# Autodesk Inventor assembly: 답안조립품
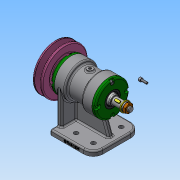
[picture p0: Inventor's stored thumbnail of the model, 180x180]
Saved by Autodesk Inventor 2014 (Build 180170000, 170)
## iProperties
Created: 2020-06
Part Number: 답안조립품
Document SubType Name: Assembly
Designer: net
Author: net
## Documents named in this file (12)
- C:\Users\net\Desktop\700606V1006\답안조립품.iam
- C:\Users\net\Desktop\700606V1006\본체.ipt
- C:\Users\net\Desktop\700606V1006\V-벨트풀리.ipt
- C:\Users\net\Desktop\700606V1006\너트 M10.ipt
- C:\Users\net\Desktop\700606V1006\베어링 6204.ipt
- C:\Users\net\Desktop\700606V1006\볼트 M4.ipt
- C:\Users\net\Desktop\700606V1006\스프링 와셔 10.ipt
- C:\Users\net\Desktop\700606V1006\오일 실 20 32 5.ipt
- C:\Users\net\Desktop\700606V1006\축.ipt
- C:\Users\net\Desktop\700606V1006\커버.ipt
- C:\Users\net\Desktop\700606V1006\키 5x5x12.ipt
- C:\Users\net\Desktop\700606V1006\평면 와셔 10x21.ipt
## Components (2 placed, 1 different names)
1. V-벨트풀리:1
2. V-벨트풀리:2
